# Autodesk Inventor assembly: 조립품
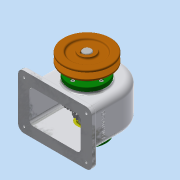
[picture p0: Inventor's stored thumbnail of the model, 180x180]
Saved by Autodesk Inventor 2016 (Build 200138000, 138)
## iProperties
Created: 2018-11
Part Number: 조립품
Material: 일반
Document SubType Name: Assembly
Designer: user
Author: user
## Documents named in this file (14)
- C:\Users\user\Desktop\481111V1007\조립품.iam
- C:\Users\user\Desktop\481111V1007\V-벨트풀리.ipt
- C:\Users\user\Desktop\481111V1007\뒤커버.ipt
- C:\Users\user\Desktop\481111V1007\멈춤나사 M4.ipt
- C:\Users\user\Desktop\481111V1007\베어링 6203.ipt
- C:\Users\user\Desktop\481111V1007\본체.ipt
- C:\Users\user\Desktop\481111V1007\볼트 M4.ipt
- C:\Users\user\Desktop\481111V1007\부시.ipt
- C:\Users\user\Desktop\481111V1007\스퍼기어.ipt
- C:\Users\user\Desktop\481111V1007\앞커버.ipt
- C:\Users\user\Desktop\481111V1007\오일 실 28 40 8.ipt
- C:\Users\user\Desktop\481111V1007\축.ipt
- C:\Users\user\Desktop\481111V1007\키 5x5x18.ipt
- C:\Users\user\Desktop\481111V1007\키 6x6x22.ipt
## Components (1 placed, 1 different names)
1. V-벨트풀리:1
